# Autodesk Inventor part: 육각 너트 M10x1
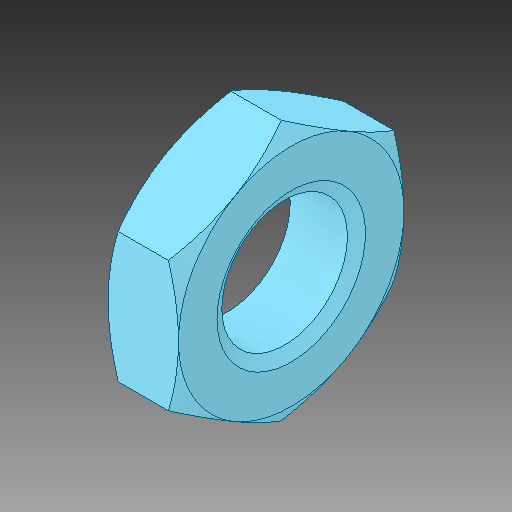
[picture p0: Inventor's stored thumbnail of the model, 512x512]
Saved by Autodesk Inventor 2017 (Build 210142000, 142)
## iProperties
Created: 2024-09
Part Number: 육각 너트 M10x1
Material: 일반
Description: 6각 너트 및 6각 가는 너트 - 이중 모따기
Document SubType Name: Modeling
Designer: MRC
Density: 1 g/cm^3
Appearance: 기본값
Author: jhkim
Sending System: Autodesk Inventor 2025
Preprocessor: ST-DEVELOPER v20
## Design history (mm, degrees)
feature "Solid1"
node "솔리드1"
